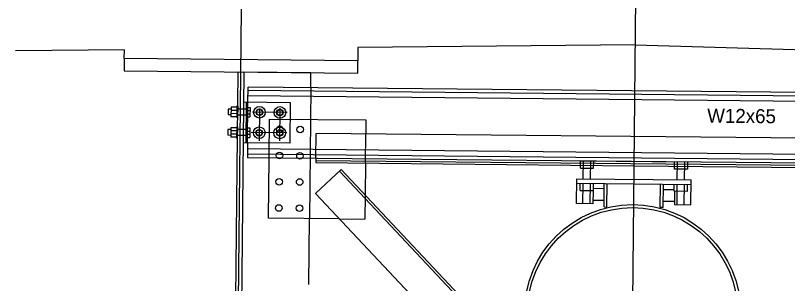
# Model space of a CAD drawing. Extents: x 632312 to 632425, y 378332 to 378413.
# Drawn here: x 632360.22 to 632371.24, y 378392.39 to 378396.22 of the extents above; entities that cross this region are included whole.
import ezdxf

# ---------------------------------------------------------------- set-up
doc = ezdxf.new("R2010")
doc.units = 0
for name, color, linetype in [('B_Boring', 7, 'Continuous'), ('B_Boring Annot', 7, 'Continuous'), ('R_Proposed Const Limits Cut', 7, 'Continuous'), ('R_Road Edge of Shoulder', 7, 'Continuous'), ('R_Shade Removal', 7, 'Continuous'), ('R_Wall', 7, 'Continuous'), ('SHT_Dimensions', 7, 'Continuous')]:
    doc.layers.add(name, color=color, linetype=linetype)

msp = doc.modelspace()

# ---------------------------------------------------------------- linework, layer by layer
at = {"layer": 'B_Boring'}
for p, q in [((632363.536, 378394.982), (632363.538, 378395.195)), ((632374.579, 378395.085), (632363.538, 378395.195)), ((632374.579, 378395.034), (632363.538, 378395.144)), ((632363.296, 378394.906), (632363.294, 378394.771)), ((632363.379, 378394.906), (632363.296, 378394.906)), ((632363.379, 378394.921), (632363.378, 378394.755)), ((632363.39, 378394.921), (632363.379, 378394.921)), ((632363.39, 378394.921), (632363.388, 378394.754)), ((632363.474, 378394.983), (632364.14, 378394.976)), ((632363.51, 378394.399), (632363.515, 378394.982)), ((632364.14, 378394.976), (632364.134, 378394.393)), ((632363.254, 378394.881), (632363.253, 378394.797)), ((632363.295, 378394.797), (632363.253, 378394.797)), ((632363.296, 378394.88), (632363.254, 378394.881)), ((632363.379, 378394.86), (632363.295, 378394.861)), ((632363.378, 378394.815), (632363.295, 378394.816)), ((632363.515, 378394.904), (632363.513, 378394.769)), ((632363.514, 378394.859), (632363.566, 378394.859)), ((632363.514, 378394.814), (632363.566, 378394.813)), ((632363.515, 378394.904), (632363.567, 378394.904)), ((632363.567, 378394.904), (632363.565, 378394.768)), ((632363.378, 378394.77), (632363.294, 378394.771)), ((632363.388, 378394.754), (632363.378, 378394.755)), ((632363.513, 378394.769), (632363.565, 378394.768)), ((632365.221, 378394.726), (632365.221, 378394.726)), ((632363.251, 378394.589), (632363.25, 378394.506)), ((632363.293, 378394.589), (632363.251, 378394.589)), ((632363.293, 378394.615), (632363.292, 378394.479)), ((632363.376, 378394.614), (632363.293, 378394.615)), ((632363.376, 378394.63), (632363.375, 378394.463)), ((632363.387, 378394.629), (632363.376, 378394.63)), ((632363.387, 378394.629), (632363.385, 378394.463)), ((632363.512, 378394.613), (632363.51, 378394.477)), ((632363.512, 378394.613), (632363.564, 378394.612)), ((632363.564, 378394.612), (632363.562, 378394.477)), ((632363.292, 378394.505), (632363.25, 378394.506)), ((632363.376, 378394.569), (632363.292, 378394.57)), ((632363.375, 378394.524), (632363.292, 378394.524)), ((632363.375, 378394.479), (632363.292, 378394.479)), ((632363.51, 378394.477), (632363.562, 378394.477)), ((632363.511, 378394.567), (632363.563, 378394.567)), ((632363.511, 378394.522), (632363.563, 378394.522)), ((632363.385, 378394.463), (632363.375, 378394.463)), ((632364.134, 378394.393), (632363.468, 378394.399)), ((632363.53, 378394.399), (632363.528, 378394.186)), ((632374.569, 378394.077), (632363.528, 378394.186)), ((632374.57, 378394.127), (632363.529, 378394.237)), ((632363.832, 378393.323), (632363.841, 378394.183)), ((632364.507, 378394.177), (632364.507, 378394.116)), ((632368.282, 378394.037), (632368.283, 378394.139)), ((632369.815, 378394.122), (632368.283, 378394.137)), ((632368.323, 378393.884), (632368.325, 378394.139)), ((632368.427, 378393.883), (632368.43, 378394.138)), ((632368.471, 378394.035), (632368.472, 378394.137)), ((632364.507, 378394.116), (632369.048, 378394.071)), ((632368.282, 378394.037), (632368.471, 378394.035)), ((632369.048, 378394.071), (632373.59, 378394.026)), ((632369.624, 378394.024), (632369.626, 378394.126)), ((632369.814, 378394.022), (632369.624, 378394.024)), ((632369.665, 378393.871), (632369.668, 378394.125)), ((632369.77, 378393.869), (632369.772, 378394.124)), ((632369.814, 378394.022), (632369.815, 378394.124)), ((632368.227, 378393.53), (632368.23, 378393.885)), ((632368.229, 378393.822), (632369.862, 378393.805)), ((632368.23, 378393.885), (632369.862, 378393.869)), ((632368.279, 378393.719), (632368.28, 378393.821)), ((632368.319, 378393.529), (632368.322, 378393.821)), ((632368.424, 378393.528), (632368.427, 378393.82)), ((632368.468, 378393.717), (632368.469, 378393.819)), ((632368.621, 378393.482), (632368.624, 378393.818)), ((632368.662, 378393.481), (632368.665, 378393.817)), ((632369.423, 378393.474), (632369.426, 378393.81)), ((632369.464, 378393.473), (632369.467, 378393.809)), ((632369.621, 378393.706), (632369.622, 378393.808)), ((632369.662, 378393.516), (632369.665, 378393.807)), ((632369.766, 378393.515), (632369.769, 378393.806)), ((632369.811, 378393.704), (632369.812, 378393.806)), ((632369.859, 378393.514), (632369.862, 378393.869)), ((632368.279, 378393.719), (632368.468, 378393.717)), ((632368.463, 378393.717), (632368.461, 378393.528)), ((632368.624, 378393.743), (632368.468, 378393.744)), ((632369.466, 378393.734), (632369.622, 378393.733)), ((632369.811, 378393.704), (632369.621, 378393.706)), ((632369.627, 378393.706), (632369.625, 378393.516)), ((632368.461, 378393.528), (632368.227, 378393.53)), ((632368.622, 378393.575), (632368.461, 378393.576)), ((632368.621, 378393.482), (632368.662, 378393.481)), ((632369.464, 378393.473), (632369.423, 378393.474)), ((632369.465, 378393.566), (632369.625, 378393.565)), ((632369.625, 378393.516), (632369.859, 378393.514)), ((632364.842, 378393.313), (632363.832, 378393.323))]:
    msp.add_line(p, q, dxfattribs=at)
for points in [[(632365.103, 378395.394), (632365.105, 378395.571), (632361.771, 378395.604), (632361.77, 378395.427)], [(632363.359, 378383.41), (632363.275, 378383.411), (632363.395, 378395.411), (632363.478, 378395.41)]]:
    msp.add_lwpolyline(points, close=True, dxfattribs=at)
for points in [[(632364.434, 378395.186), (632364.436, 378395.4), (632363.478, 378395.41), (632363.359, 378383.41), (632364.317, 378383.401), (632364.318, 378383.526)], [(632365.215, 378394.109), (632365.211, 378393.651)], [(632366.976, 378391.039), (632364.502, 378393.675), (632364.867, 378394.017), (632366.983, 378391.762)], [(632364.406, 378392.373), (632364.415, 378393.317)]]:
    msp.add_lwpolyline(points, dxfattribs=at)
for centre, radius in [((632363.701, 378394.835), 0.0469), ((632363.993, 378394.832), 0.0469), ((632363.698, 378394.543), 0.0469), ((632363.99, 378394.54), 0.0469), ((632363.991, 378394.592), 0.0469), ((632364.282, 378394.589), 0.0469), ((632363.987, 378394.217), 0.0469), ((632364.279, 378394.214), 0.0469), ((632363.983, 378393.842), 0.0469), ((632364.275, 378393.839), 0.0469), ((632363.979, 378393.467), 0.0469), ((632364.271, 378393.464), 0.0469), ((632369.027, 378391.974), 1.542), ((632369.027, 378391.974), 1.5)]:
    msp.add_circle(centre, radius, dxfattribs=at)
at = {"layer": 'B_Boring Annot'}
for p, q in [((632369.065, 378395.8), (632365.106, 378395.76)), ((632369.065, 378395.8), (632373.023, 378395.682)), ((632361.773, 378395.727), (632360.217, 378395.711)), ((632361.771, 378395.604), (632361.773, 378395.727)), ((632365.106, 378395.76), (632365.105, 378395.571)), ((632365.105, 378395.571), (632361.771, 378395.604))]:
    msp.add_line(p, q, dxfattribs=at)
at = {"layer": 'R_Proposed Const Limits Cut'}
for p, q in [((632364.434, 378395.186), (632364.415, 378393.317)), ((632374.578, 378394.96), (632363.537, 378395.07)), ((632363.53, 378394.399), (632363.536, 378394.982)), ((632363.513, 378394.795), (632363.388, 378394.796)), ((632363.514, 378394.878), (632363.389, 378394.879)), ((632363.841, 378394.183), (632363.846, 378394.739)), ((632363.846, 378394.739), (632365.221, 378394.726)), ((632365.221, 378394.726), (632365.219, 378394.526)), ((632363.511, 378394.587), (632363.386, 378394.588)), ((632363.511, 378394.503), (632363.386, 378394.504)), ((632364.507, 378394.177), (632364.511, 378394.533)), ((632373.594, 378394.443), (632364.511, 378394.533)), ((632365.215, 378394.109), (632365.219, 378394.526)), ((632374.571, 378394.202), (632363.529, 378394.311)), ((632373.59, 378394.052), (632364.507, 378394.142)), ((632364.844, 378393.996), (632373.475, 378384.8)), ((632365.211, 378393.651), (632365.207, 378393.309)), ((632364.842, 378393.313), (632365.207, 378393.309))]:
    msp.add_line(p, q, dxfattribs=at)
for centre, radius in [((632363.701, 378394.835), 0.0833), ((632363.993, 378394.832), 0.0833), ((632363.701, 378394.835), 0.0417), ((632363.993, 378394.832), 0.0417), ((632363.698, 378394.543), 0.0833), ((632363.698, 378394.543), 0.0417), ((632363.99, 378394.54), 0.0833), ((632363.99, 378394.54), 0.0417)]:
    msp.add_circle(centre, radius, dxfattribs=at)
at = {"layer": 'R_Road Edge of Shoulder'}
msp.add_line((632368.897, 378378.888), (632369.228, 378412.129), dxfattribs=at)
at = {"layer": 'R_Shade Removal'}
msp.add_line((632363.305, 378382.234), (632363.445, 378396.306), dxfattribs=at)
at = {"layer": 'R_Wall'}
for p, q in [((632364.097, 378394.831), (632363.603, 378394.836)), ((632363.702, 378394.889), (632363.697, 378394.426)), ((632363.994, 378394.892), (632363.989, 378394.427)), ((632364.094, 378394.539), (632363.584, 378394.544))]:
    msp.add_line(p, q, dxfattribs=at)
at = {"layer": 'SHT_Dimensions'}
msp.add_line((632363.474, 378394.983), (632363.468, 378394.399), dxfattribs=at)
msp.add_circle((632363.701, 378394.835), 0.0469, dxfattribs=at)

# ---------------------------------------------------------------- texts
msp.add_text('W12x65', height=0.2, rotation=359.4304, dxfattribs=at).set_placement((632370.092, 378394.687))

doc.saveas('drawing.dxf')
